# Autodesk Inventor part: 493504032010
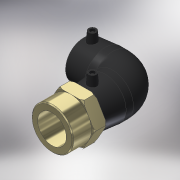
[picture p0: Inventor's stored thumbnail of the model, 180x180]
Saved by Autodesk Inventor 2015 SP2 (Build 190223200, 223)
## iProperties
Created: 2017-06
Part Number: 493504032010
Material: Generic
Description: PLASSON 90° ELBOW FEMALE TRANSITION 32-1''
Document SubType Name: Modeling
Designer: KIM
Mass: 126.164 g
Surface Area: 386.902 cm^2
Volume: 126.164 cm^3
Density: 1 g/cm^3
Appearance: Rubber - Black
Author: KIM
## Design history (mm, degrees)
derived "493504.ipt"
feature "Solid1::493504.ipt"
tag "TaggingFeature1"
body "Solid1"
other parameters: "d2" = 44, "d4" = 27.66667, "d5" = 39.6, "d8" = 168 deg, "d10" = 16, "d11" = 5.33333, "d29" = 43, "d30" = 15, "d31" = 45.65, "d34" = 5 deg, "d41" = 4, "d42" = 14, "d43" = 0, "d48" = 61, "d49" = 32, "d50" = 27.2, "d51" = 16, "d54" = 90 deg, "d57" = 32, "d59" = 0, "d61" = 90 deg, "d86" = 3, "d87" = 0, "d93" = 0.1, "d96" = 30.291, "d97" = 23, "d98" = 25, "d99" = 44, "d108" = 0, "d109" = 0.96, "d112" = 45 deg, "d113" = 45 deg, "d114" = 1.6, "d_" = 32, "L_" = 108, "D_" = 23, "A_" = 43, "d_2" = 12, "L_2" = 25, "D_1" = 44, "Rp_" = 30.291
